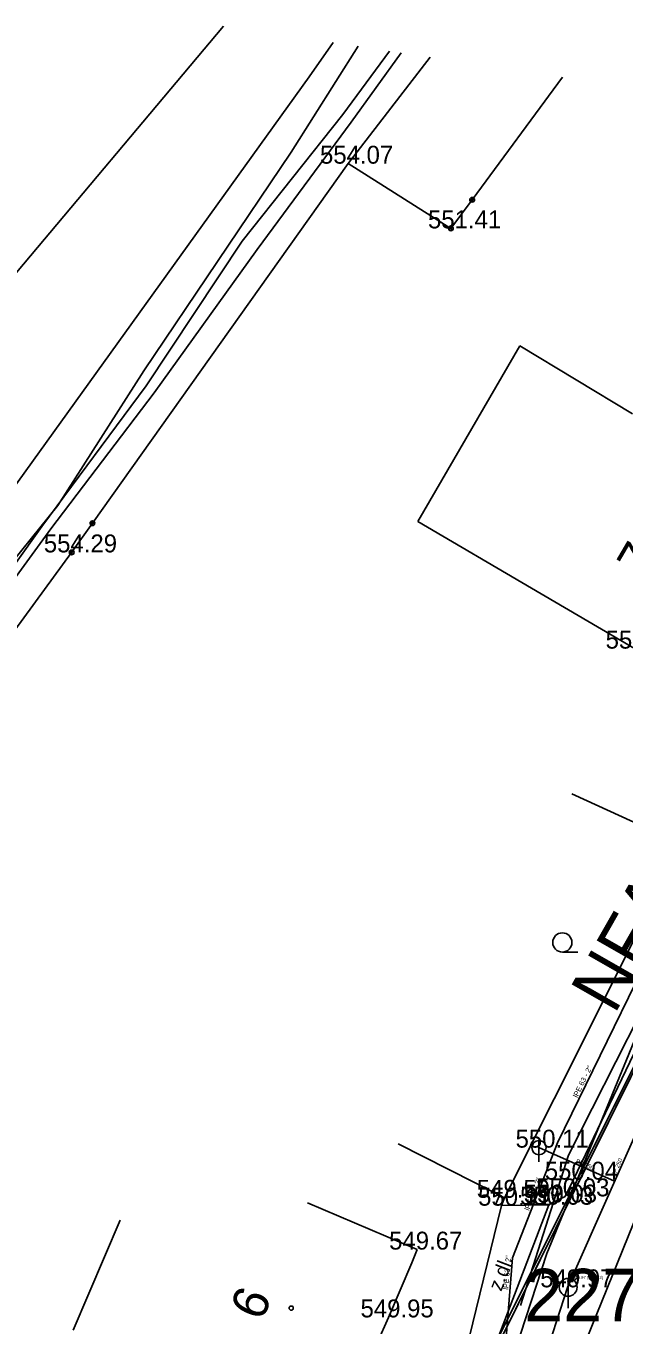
# Model space of a CAD drawing. Extents: x -669995 to -669686, y -1125551 to -1125263.
# Drawn here: x -669842.4 to -669817.3, y -1125325.7 to -1125271.2 of the extents above; entities that cross this region are included whole.
import ezdxf

# ---------------------------------------------------------------- set-up
doc = ezdxf.new("R2010")
doc.units = 0
for name, color, linetype in [('G_Bod_tecka', 7, 'Continuous'), ('G_Bod_vyska', 7, 'Continuous'), ('G_Breh_Teren', 7, 'Continuous'), ('G_Budovy-znacky', 7, 'Continuous'), ('G_Budovy_Objekty', 7, 'Continuous'), ('G_Budovy_vstupy', 7, 'Continuous'), ('G_Cesty_Schody', 7, 'Continuous'), ('G_Cisla_popisna', 7, 'Continuous'), ('G_Plochy_zpevnene', 7, 'Continuous'), ('G_Ploty', 7, 'Continuous'), ('G_Ploty_vstupy', 7, 'Continuous'), ('G_Popisy_povrchu', 7, 'Continuous'), ('G_Site-kanalizace', 7, 'Continuous'), ('G_Site-Sloupy', 7, 'Continuous'), ('G_Z_ELsilove_nadz_kotovane', 7, 'Continuous'), ('G_Z_ELsilove_podz_kotovane', 7, 'Continuous'), ('G_Z_ELsilove_zrusene', 7, 'Continuous'), ('G_Z_KANAL_podz_kotovane', 7, 'Continuous'), ('G_Z_PLYNY_podz_geodeticky', 7, 'Continuous'), ('G_Z_SPOJE_podz_geodeticky', 7, 'Continuous'), ('G_Z_SPOJE_podz_kotovane', 7, 'Continuous'), ('G_Z_SPOJE_podz_priblizne', 7, 'Continuous'), ('G_Z_VODA_podz_kotovane', 7, 'Continuous'), ('G_Zelen-Znacky', 7, 'Continuous'), ('Vrstva 11', 7, 'Continuous'), ('Vrstva 2', 7, 'Continuous'), ('Vrstva 21', 7, 'Continuous'), ('Vrstva 26', 7, 'Continuous'), ('Vrstva 3', 7, 'Continuous'), ('Vrstva 4', 7, 'Continuous'), ('Vrstva 5', 7, 'Continuous'), ('Vrstva 8', 7, 'Continuous')]:
    doc.layers.add(name, color=color, linetype=linetype)

msp = doc.modelspace()

# ---------------------------------------------------------------- linework, layer by layer
at = {"layer": 'G_Bod_tecka'}
for p, q in [((-669828.86, -1125276.99), (-669828.86, -1125276.99)), ((-669824.56, -1125279.7), (-669824.56, -1125279.7)), ((-669840.45, -1125293.27), (-669840.45, -1125293.27)), ((-669820.87, -1125318.2), (-669820.87, -1125318.2)), ((-669819.42, -1125319.54), (-669819.42, -1125319.54)), ((-669822.31, -1125320.3), (-669822.31, -1125320.3)), ((-669819.78, -1125320.24), (-669819.78, -1125320.24)), ((-669822.44, -1125320.63), (-669822.44, -1125320.63)), ((-669820.46, -1125320.59), (-669820.46, -1125320.59)), ((-669820.3, -1125320.5), (-669820.3, -1125320.5)), ((-669825.97, -1125322.47), (-669825.97, -1125322.47)), ((-669819.65, -1125324.05), (-669819.65, -1125324.05)), ((-669827.18, -1125325.31), (-669827.18, -1125325.31))]:
    msp.add_line(p, q, dxfattribs=at)
at = {"layer": 'G_Breh_Teren'}
for p, q in [((-669866.68, -1125309.93), (-669834.084, -1125271.224)), ((-669830.5, -1125273.35), (-669829.498, -1125271.914)), ((-669825.435, -1125272.526), (-669828.86, -1125276.98)), ((-669830.5, -1125273.35), (-669850.37, -1125300.97))]:
    msp.add_line(p, q, dxfattribs=at)
at = {"layer": 'G_Budovy-znacky'}
msp.add_circle((-669831.25, -1125324.921), 0.0875, dxfattribs=at)
at = {"layer": 'G_Budovy_Objekty'}
for p, q in [((-669821.67, -1125284.62), (-669825.94, -1125291.98)), ((-669816.95, -1125287.46), (-669821.67, -1125284.62)), ((-669825.94, -1125291.98), (-669821.18, -1125294.77)), ((-669821.18, -1125294.77), (-669816.87, -1125297.3)), ((-669830.57, -1125320.51), (-669825.97, -1125322.47)), ((-669838.42, -1125321.24), (-669840.38, -1125325.84)), ((-669826.2, -1125323.02), (-669825.97, -1125322.47)), ((-669827.63, -1125326.35), (-669827.18, -1125325.31))]:
    msp.add_line(p, q, dxfattribs=at)
at = {"layer": 'G_Budovy_vstupy'}
msp.add_line((-669827.18, -1125325.31), (-669826.2, -1125323.02), dxfattribs=at)
at = {"layer": 'G_Cesty_Schody'}
msp.add_lwpolyline([(-669820.46, -1125320.59), (-669822.6, -1125326.19)], dxfattribs=at)
at = {"layer": 'G_Plochy_zpevnene'}
for points in [[(-669805.79, -1125294.93), (-669810.6, -1125302.02), (-669813.3, -1125306.54), (-669816.06, -1125312.52), (-669819.42, -1125319.54), (-669819.78, -1125320.24), (-669820.3, -1125320.5), (-669820.46, -1125320.59)], [(-669820.46, -1125320.59), (-669822.44, -1125320.63)]]:
    msp.add_lwpolyline(points, dxfattribs=at)
at = {"layer": 'G_Ploty'}
for p, q in [((-669823.67, -1125278.5), (-669819.883, -1125273.363)), ((-669839.58, -1125292.05), (-669828.86, -1125276.98)), ((-669828.86, -1125276.98), (-669824.56, -1125279.7)), ((-669852.85, -1125310.23), (-669840.45, -1125293.27)), ((-669815.59, -1125306.88), (-669822.31, -1125320.3))]:
    msp.add_line(p, q, dxfattribs=at)
for points in [[(-669814.94, -1125305.46), (-669819.49, -1125303.38)], [(-669822.31, -1125320.3), (-669822.53, -1125320.19), (-669826.77, -1125318.04)], [(-669822.53, -1125320.19), (-669822.68, -1125320.57)], [(-669822.31, -1125320.3), (-669822.44, -1125320.63)]]:
    msp.add_lwpolyline(points, dxfattribs=at)
at = {"layer": 'G_Ploty_vstupy'}
for p, q in [((-669823.67, -1125278.5), (-669824.56, -1125279.7)), ((-669839.58, -1125292.05), (-669840.45, -1125293.27))]:
    msp.add_line(p, q, dxfattribs=at)
msp.add_lwpolyline([(-669823.95, -1125326.79), (-669822.44, -1125320.63)], dxfattribs=at)
at = {"layer": 'G_Site-kanalizace'}
for p, q in [((-669820.87, -1125317.9), (-669820.87, -1125318.8)), ((-669819.65, -1125323.675), (-669819.65, -1125324.925))]:
    msp.add_line(p, q, dxfattribs=at)
for centre, radius in [((-669820.87, -1125318.2), 0.3), ((-669819.65, -1125324.05), 0.375)]:
    msp.add_circle(centre, radius, dxfattribs=at)
at = {"layer": 'G_Site-Sloupy'}
for centre, radius in [((-669823.67, -1125278.5), 0.1), ((-669823.67, -1125278.5), 0.0348), ((-669824.56, -1125279.7), 0.1), ((-669824.56, -1125279.7), 0.0348), ((-669839.58, -1125292.05), 0.1), ((-669839.58, -1125292.05), 0.0348), ((-669840.45, -1125293.27), 0.1), ((-669840.45, -1125293.27), 0.0348)]:
    msp.add_circle(centre, radius, dxfattribs=at)
at = {"layer": 'G_Z_ELsilove_nadz_kotovane'}
msp.add_lwpolyline([(-669822.83, -1125326.67), (-669806.73, -1125294.49), (-669793.764, -1125277.296)], dxfattribs=at)
at = {"layer": 'G_Z_ELsilove_podz_kotovane'}
msp.add_lwpolyline([(-669793.678, -1125277.309), (-669806.73, -1125294.49), (-669822.69, -1125326.67), (-669837.43, -1125364.93), (-669849.93, -1125407.07), (-669860.28, -1125448.68)], dxfattribs=at)
at = {"layer": 'G_Z_ELsilove_zrusene'}
for points in [[(-669852.84, -1125307.296), (-669849.346, -1125302.7), (-669845.085, -1125296.905), (-669841.704, -1125292.183), (-669837.328, -1125286.295), (-669833.311, -1125280.239), (-669829.094, -1125274.935), (-669827.127, -1125272.272)], [(-669852.84, -1125307.296), (-669849.346, -1125302.7), (-669845.085, -1125296.905), (-669841.704, -1125292.183), (-669837.328, -1125286.295), (-669833.311, -1125280.239), (-669829.094, -1125274.935), (-669827.127, -1125272.272)], [(-669826.644, -1125272.344), (-669828.746, -1125275.251), (-669832.68, -1125280.589), (-669836.998, -1125286.582), (-669841.319, -1125292.289), (-669844.836, -1125297.104)], [(-669826.644, -1125272.344), (-669828.746, -1125275.251), (-669832.68, -1125280.589), (-669836.998, -1125286.582), (-669841.319, -1125292.289), (-669844.836, -1125297.104)]]:
    msp.add_lwpolyline(points, dxfattribs=at)
at = {"layer": 'G_Z_KANAL_podz_kotovane'}
msp.add_line((-669819.67, -1125324.06), (-669822.26, -1125331.96), dxfattribs=at)
for points in [[(-669837.47, -1125406.42), (-669844.1, -1125405.26), (-669833.36, -1125371.21), (-669821.31, -1125332.23), (-669811.44, -1125307.86), (-669795.39, -1125283.71), (-669791, -1125278.72), (-669790.199, -1125277.833)], [(-669796.02, -1125282.8), (-669812.36, -1125307.58), (-669819.67, -1125324.06)], [(-669817.7, -1125319.61), (-669817.7, -1125319.61), (-669820.87, -1125318.2)]]:
    msp.add_lwpolyline(points, dxfattribs=at)
at = {"layer": 'G_Z_PLYNY_podz_geodeticky'}
msp.add_lwpolyline([(-669837.38, -1125359.92), (-669836.39, -1125358.74), (-669831.49, -1125357.25), (-669831.11, -1125356.92), (-669827.75, -1125345.68), (-669825.44, -1125337.89), (-669825.15, -1125336.78), (-669824.89, -1125336.1), (-669824.26, -1125333.86), (-669824.2, -1125333.72), (-669824.11, -1125333.34), (-669824.01, -1125332.89), (-669822.73, -1125329.33), (-669822.53, -1125328.7), (-669820.54, -1125322.64), (-669816.69, -1125313.26), (-669812.22, -1125303.65), (-669812, -1125303.3), (-669811.72, -1125302.91), (-669809.57, -1125300.17), (-669804.79, -1125292.58), (-669800.14, -1125285.7), (-669795.88, -1125280.51), (-669793.302, -1125277.366)], dxfattribs=at)
at = {"layer": 'G_Z_SPOJE_podz_geodeticky'}
for points in [[(-669828.452, -1125272.072), (-669831.26, -1125276.51), (-669837.42, -1125285.67), (-669841.03, -1125291.3), (-669843.66, -1125294.55), (-669845.85, -1125296.86), (-669849.47, -1125301.37), (-669854.59, -1125308.59), (-669859.72, -1125316.49), (-669867.4, -1125330.53), (-669869.08, -1125333.05), (-669871.26, -1125335.24), (-669875.67, -1125341.76), (-669879.69, -1125348.67), (-669882.04, -1125353.23), (-669888.47, -1125362.55)], [(-669821.65, -1125324.81), (-669819.63, -1125318.51), (-669812.69, -1125304.83), (-669803.17, -1125290.27), (-669793.576, -1125277.325)]]:
    msp.add_lwpolyline(points, dxfattribs=at)
at = {"layer": 'G_Z_SPOJE_podz_kotovane'}
msp.add_lwpolyline([(-669821.65, -1125324.81), (-669819.63, -1125318.51), (-669812.69, -1125304.83), (-669803.17, -1125290.27), (-669793.576, -1125277.325)], dxfattribs=at)
at = {"layer": 'G_Z_SPOJE_podz_priblizne'}
msp.add_lwpolyline([(-669821.65, -1125324.81), (-669819.63, -1125318.51), (-669812.69, -1125304.83), (-669803.17, -1125290.27), (-669793.576, -1125277.325)], dxfattribs=at)
at = {"layer": 'G_Z_VODA_podz_kotovane'}
msp.add_lwpolyline([(-669793.904, -1125277.275), (-669806.05, -1125295.04), (-669809.12, -1125297.97), (-669810.25, -1125299.77), (-669811.13, -1125301.2), (-669814.74, -1125307.05), (-669820.1, -1125318), (-669821.98, -1125322.82), (-669822.36, -1125327.56), (-669822.7, -1125328.38), (-669827.24, -1125342.56), (-669833.54, -1125362.52), (-669834.09, -1125363.24)], dxfattribs=at)
at = {"layer": 'G_Zelen-Znacky'}
msp.add_line((-669819.892, -1125310.01), (-669819.242, -1125310.007), dxfattribs=at)
msp.add_circle((-669819.892, -1125309.607), 0.403, dxfattribs=at)
at = {"layer": 'Vrstva 11'}
msp.add_line((-669819.67, -1125324.06), (-669822.26, -1125331.96), dxfattribs=at)
for points in [[(-669796.02, -1125282.8), (-669812.36, -1125307.58), (-669819.67, -1125324.06)], [(-669817.697, -1125319.611), (-669817.7, -1125319.61), (-669820.87, -1125318.2)]]:
    msp.add_lwpolyline(points, dxfattribs=at)
at = {"layer": 'Vrstva 21'}
msp.add_lwpolyline([(-669837.47, -1125406.42), (-669844.1, -1125405.26), (-669833.36, -1125371.21), (-669821.31, -1125332.23), (-669811.44, -1125307.86), (-669795.39, -1125283.71), (-669791, -1125278.72), (-669790.199, -1125277.833)], dxfattribs=at)
at = {"layer": 'Vrstva 26'}
msp.add_lwpolyline([(-669793.906, -1125277.275), (-669806.05, -1125295.04), (-669809.12, -1125297.97), (-669810.25, -1125299.77), (-669811.134, -1125301.203), (-669814.74, -1125307.05), (-669820.1, -1125318), (-669821.98, -1125322.82), (-669822.36, -1125327.56), (-669822.7, -1125328.38), (-669827.24, -1125342.56), (-669833.535, -1125362.519), (-669834.09, -1125363.24)], dxfattribs=at)
at = {"layer": 'Vrstva 5'}
msp.add_line((-669806.73, -1125294.49), (-669822.69, -1125326.67), dxfattribs=at)
at = {"layer": 'Vrstva 8'}
for p, q in [((-669820.87, -1125318.2), (-669820.87, -1125318.2)), ((-669819.67, -1125324.06), (-669819.67, -1125324.06))]:
    msp.add_line(p, q, dxfattribs=at)

# ---------------------------------------------------------------- texts
at = {"layer": 'G_Bod_vyska'}
for s, p in [('554.07', (-669830.046, -1125276.99)), ('551.41', (-669825.521, -1125279.7)), ('554.29', (-669841.616, -1125293.27)), ('550.09', (-669818.079, -1125297.3)), ('550.11', (-669821.852, -1125318.2)), ('550.04', (-669820.627, -1125319.54)), ('549.59', (-669823.478, -1125320.3)), ('550.03', (-669821.665, -1125320.59)), ('550.03', (-669821.507, -1125320.5)), ('550.03', (-669820.987, -1125320.24)), ('550.11', (-669823.422, -1125320.63)), ('549.67', (-669827.15, -1125322.47)), ('549.97', (-669820.818, -1125324.05)), ('549.95', (-669828.348, -1125325.31))]:
    msp.add_text(s, height=0.75, dxfattribs=at).set_placement(p)
at = {"layer": 'G_Cisla_popisna'}
for s, rotation, p in [('73', 59.6209, (-669816.381, -1125294.412)), ('6', 66.5685, (-669832.484, -1125325.506))]:
    msp.add_text(s, height=1.5, rotation=rotation, dxfattribs=at).set_placement(p)
at = {"layer": 'G_Popisy_povrchu'}
msp.add_text('z.dl.', height=0.6, rotation=69.0503, dxfattribs=at).set_placement((-669822.452, -1125324.247))
at = {"layer": 'Vrstva 2'}
for s, height, p in [('\xa0()', 0.1316, (-669821.277, -1125318.061)), ('549.97 (548.52)', 0.13163, (-669819.464, -1125323.707))]:
    msp.add_text(s, height=height, dxfattribs=at).set_placement(p)
at = {"layer": 'Vrstva 3'}
for s, height, rotation, p in [('NFA2X 2x25 2x25', 2.19389, 60.2692, (-669817.715, -1125312.66)), ('PP 150', 0.1755, 336.0166, (-669819.342, -1125318.822)), ('PP 250', 0.1755, 66.071, (-669817.689, -1125319.42))]:
    msp.add_text(s, height=height, rotation=rotation, dxfattribs=at).set_placement(p)
at = {"layer": 'Vrstva 4'}
for rotation, p in [(63.916, (-669819.262, -1125316.127)), (68.6381, (-669821.289, -1125320.855)), (85.4132, (-669822.157, -1125324.155))]:
    msp.add_text('lPE 63 - 2"', height=0.21938, rotation=rotation, dxfattribs=at).set_placement(p)
msp.add_text('2275', height=2.1939, dxfattribs=at).set_placement((-669821.487, -1125325.469))

doc.saveas('drawing.dxf')
